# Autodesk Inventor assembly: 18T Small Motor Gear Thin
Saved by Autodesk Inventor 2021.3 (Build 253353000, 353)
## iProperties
Created: 2022-05
Part Number: 18T Small Motor Gear Thin
Document SubType Name: Assembly
Designer: Administrator
Title: 18T Small Motor Gear Thin v2
Author: Administrator
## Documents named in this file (2)
- c:\worker\convert-fusion-r03\tmp\job-1\189\output\files\c75d72c0-8811-46da-8334-718858ca81d8\3f3eabb3-1a16-456c-b7f3-e1e0704b7901.iam
- c:\worker\convert-fusion-r03\tmp\job-1\189\output\files\c75d72c0-8811-46da-8334-718858ca81d8\Component1.ipt
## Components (1 placed, 1 different names)
1. Component1:1
